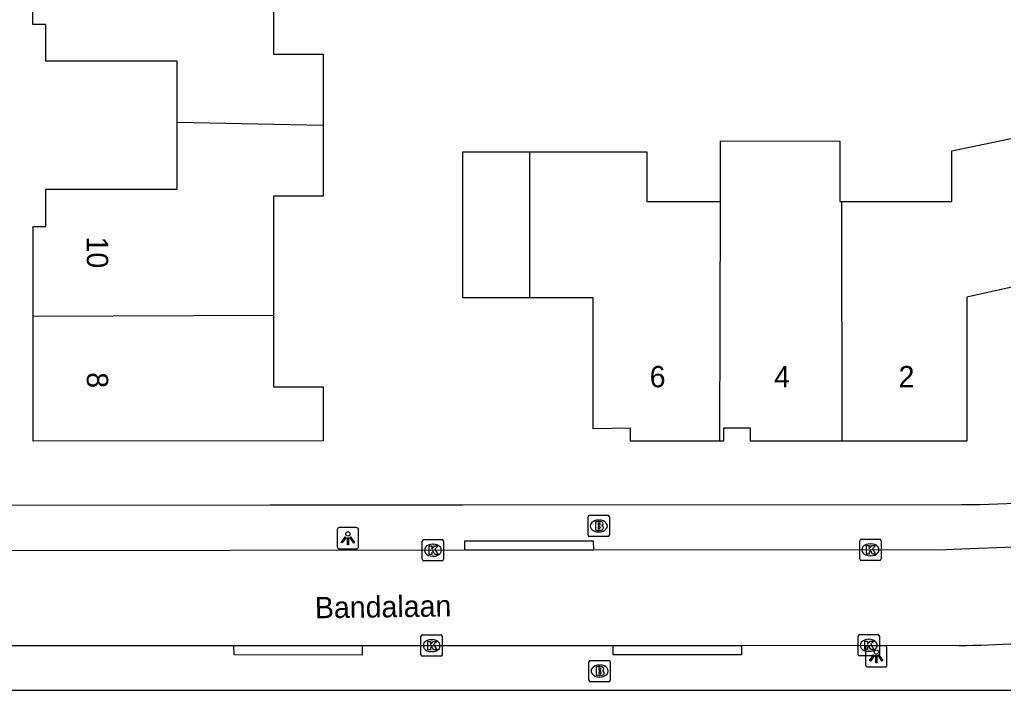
# Model space of a CAD drawing. Extents: x 162880 to 165536, y 384011 to 385179.
# Drawn here: x 163806.79 to 163852.88, y 384309.18 to 384340.61 of the extents above; entities that cross this region are included whole.
import ezdxf

# ---------------------------------------------------------------- set-up
doc = ezdxf.new("R2010")
doc.units = 0
for name, color, linetype in [('IMGEO_Brandkraan', 7, 'Continuous'), ('IMGEO_Kolk', 7, 'Continuous'), ('IMGEO_Lichtpunt', 7, 'Continuous'), ('IMGEO_Muur', 7, 'Continuous'), ('IMGEO_Openbare_ruimte_label', 7, 'Continuous'), ('IMGEO_Pand', 7, 'Continuous'), ('IMGEO_Pand_nummerreeks', 7, 'Continuous'), ('IMGEO_Rijbaan_lokaal_gesloten', 7, 'Continuous'), ('IMGEO_Voetpad_open', 7, 'Continuous')]:
    doc.layers.add(name, color=color, linetype=linetype)

msp = doc.modelspace()

# ---------------------------------------------------------------- linework, layer by layer
at = {"layer": 'IMGEO_Brandkraan'}
for p, q in [((163833.422, 384316.46), (163833.422, 384317.312)), ((163833.497, 384317.386), (163834.349, 384317.386)), ((163833.91, 384317.166), (163833.935, 384317.166)), ((163834.423, 384317.312), (163834.423, 384316.46)), ((163834.349, 384316.386), (163833.497, 384316.386)), ((163833.933, 384316.606), (163833.908, 384316.606)), ((163833.459, 384309.662), (163833.459, 384310.514)), ((163833.534, 384310.588), (163834.386, 384310.588)), ((163833.947, 384310.368), (163833.972, 384310.368)), ((163834.46, 384310.514), (163834.46, 384309.662)), ((163833.97, 384309.808), (163833.945, 384309.808)), ((163834.386, 384309.588), (163833.534, 384309.588))]:
    msp.add_line(p, q, dxfattribs=at)
for points in [[(163833.422, 384316.46), (163833.422, 384317.312)], [(163833.497, 384317.386), (163834.349, 384317.386)], [(163834.423, 384317.312), (163834.423, 384316.46)], [(163833.77, 384317.086), (163833.77, 384316.686), (163833.983, 384316.686)], [(163834.001, 384317.086), (163833.77, 384317.086)], [(163833.949, 384317.005), (163833.895, 384317.005), (163833.895, 384316.929)], [(163833.895, 384316.929), (163833.948, 384316.929)], [(163833.957, 384316.853), (163833.895, 384316.853), (163833.895, 384316.772)], [(163833.895, 384316.772), (163833.957, 384316.772)], [(163834.349, 384316.386), (163833.497, 384316.386)], [(163833.459, 384309.662), (163833.459, 384310.514)], [(163833.534, 384310.588), (163834.386, 384310.588)], [(163833.807, 384310.288), (163833.807, 384309.888), (163834.02, 384309.888)], [(163834.038, 384310.288), (163833.807, 384310.288)], [(163834.46, 384310.514), (163834.46, 384309.662)], [(163833.986, 384310.207), (163833.932, 384310.207), (163833.932, 384310.131)], [(163833.932, 384310.131), (163833.985, 384310.131)], [(163833.994, 384310.055), (163833.932, 384310.055), (163833.932, 384309.974)], [(163833.932, 384309.974), (163833.994, 384309.974)], [(163834.386, 384309.588), (163833.534, 384309.588)]]:
    msp.add_lwpolyline(points, dxfattribs=at)
for centre, radius, start, end in [((163833.499, 384317.31), 0.0765, 91.552, 178.448), ((163833.499, 384317.31), 0.0765, 91.552, 178.448), ((163834.347, 384317.31), 0.0765, 1.552, 88.448), ((163834.347, 384317.31), 0.0765, 1.552, 88.448), ((163833.95, 384316.967), 0.0379, 267.8285, 90.9355), ((163833.958, 384316.812), 0.0404, 269.8759, 90.5077), ((163833.989, 384316.937), 0.251, 268.6676, 293.5347), ((163834.005, 384316.941), 0.145, 59.4692, 91.5367), ((163834.03, 384316.988), 0.0922, 285.5137, 58.1501), ((163834.035, 384316.796), 0.105, 301.3115, 78.989), ((163833.499, 384316.462), 0.0765, 181.552, 268.448), ((163833.499, 384316.462), 0.0765, 181.552, 268.448), ((163834.347, 384316.462), 0.0765, 271.552, 358.448), ((163834.347, 384316.462), 0.0765, 271.552, 358.448), ((163833.536, 384310.512), 0.0765, 91.552, 178.448), ((163833.536, 384310.512), 0.0765, 91.552, 178.448), ((163834.042, 384310.143), 0.145, 59.4692, 91.5367), ((163834.067, 384310.19), 0.0922, 285.5137, 58.1501), ((163834.384, 384310.512), 0.0765, 1.552, 88.448), ((163834.384, 384310.512), 0.0765, 1.552, 88.448), ((163833.987, 384310.169), 0.0379, 267.8285, 90.9355), ((163833.995, 384310.014), 0.0404, 269.8759, 90.5077), ((163834.026, 384310.139), 0.251, 268.6676, 293.5347), ((163834.072, 384309.998), 0.105, 301.3115, 78.989), ((163833.536, 384309.664), 0.0765, 181.552, 268.448), ((163833.536, 384309.664), 0.0765, 181.552, 268.448), ((163834.384, 384309.664), 0.0765, 271.552, 358.448), ((163834.384, 384309.664), 0.0765, 271.552, 358.448)]:
    msp.add_arc(centre, radius, start, end, dxfattribs=at)
for centre, major_axis, ratio, start_param, end_param in [((163833.909, 384316.886), (-0.387, 0.002), 0.722429, 4.712389, 7.853982), ((163833.934, 384316.886), (-0.39, 0.002), 0.717154, 1.570796, 4.712389), ((163833.946, 384310.088), (-0.387, 0.002), 0.722429, 4.712389, 7.853982), ((163833.971, 384310.088), (-0.39, 0.002), 0.717154, 1.570796, 4.712389)]:
    msp.add_ellipse(centre, major_axis=major_axis, ratio=ratio, start_param=start_param, end_param=end_param, dxfattribs=at)
at = {"layer": 'IMGEO_Kolk'}
for p, q in [((163825.727, 384316.249), (163826.579, 384316.249)), ((163846.224, 384316.269), (163847.076, 384316.269)), ((163825.652, 384315.323), (163825.652, 384316.175)), ((163826.14, 384316.029), (163826.165, 384316.029)), ((163826.653, 384316.175), (163826.653, 384315.323)), ((163846.149, 384315.343), (163846.149, 384316.195)), ((163846.637, 384316.049), (163846.662, 384316.049)), ((163847.15, 384316.195), (163847.15, 384315.343)), ((163826.163, 384315.469), (163826.138, 384315.469)), ((163846.66, 384315.489), (163846.635, 384315.489)), ((163826.579, 384315.249), (163825.727, 384315.249)), ((163847.076, 384315.269), (163846.224, 384315.269)), ((163825.591, 384310.852), (163825.591, 384311.704)), ((163825.666, 384311.778), (163826.518, 384311.778)), ((163826.592, 384311.704), (163826.592, 384310.852)), ((163846.071, 384310.869), (163846.071, 384311.721)), ((163846.146, 384311.795), (163846.998, 384311.795)), ((163847.072, 384311.721), (163847.072, 384310.869)), ((163826.079, 384311.558), (163826.104, 384311.558)), ((163846.559, 384311.575), (163846.584, 384311.575)), ((163826.518, 384310.778), (163825.666, 384310.778)), ((163826.102, 384310.998), (163826.077, 384310.998)), ((163846.998, 384310.795), (163846.146, 384310.795)), ((163846.582, 384311.015), (163846.557, 384311.015))]:
    msp.add_line(p, q, dxfattribs=at)
for points in [[(163825.727, 384316.249), (163826.579, 384316.249)], [(163846.224, 384316.269), (163847.076, 384316.269)], [(163825.652, 384315.323), (163825.652, 384316.175)], [(163825.973, 384315.949), (163826.096, 384315.949), (163826.096, 384315.798), (163826.226, 384315.949), (163826.39, 384315.949), (163826.244, 384315.798), (163826.397, 384315.549), (163826.245, 384315.549), (163826.16, 384315.713), (163826.096, 384315.646), (163826.096, 384315.549), (163825.973, 384315.549), (163825.973, 384315.949)], [(163826.653, 384316.175), (163826.653, 384315.323)], [(163846.149, 384315.343), (163846.149, 384316.195)], [(163846.47, 384315.969), (163846.593, 384315.969), (163846.593, 384315.818), (163846.723, 384315.969), (163846.887, 384315.969), (163846.741, 384315.818), (163846.894, 384315.569), (163846.742, 384315.569), (163846.657, 384315.733), (163846.593, 384315.666), (163846.593, 384315.569), (163846.47, 384315.569), (163846.47, 384315.969)], [(163847.15, 384316.195), (163847.15, 384315.343)], [(163826.579, 384315.249), (163825.727, 384315.249)], [(163847.076, 384315.269), (163846.224, 384315.269)], [(163825.591, 384310.852), (163825.591, 384311.704)], [(163825.666, 384311.778), (163826.518, 384311.778)], [(163826.592, 384311.704), (163826.592, 384310.852)], [(163846.071, 384310.869), (163846.071, 384311.721)], [(163846.146, 384311.795), (163846.998, 384311.795)], [(163847.072, 384311.721), (163847.072, 384310.869)], [(163825.912, 384311.478), (163826.035, 384311.478), (163826.035, 384311.327), (163826.165, 384311.478), (163826.329, 384311.478), (163826.183, 384311.327), (163826.336, 384311.078), (163826.184, 384311.078), (163826.099, 384311.242), (163826.035, 384311.175), (163826.035, 384311.078), (163825.912, 384311.078), (163825.912, 384311.478)], [(163846.392, 384311.495), (163846.515, 384311.495), (163846.515, 384311.344), (163846.645, 384311.495), (163846.809, 384311.495), (163846.663, 384311.344), (163846.816, 384311.095), (163846.664, 384311.095), (163846.579, 384311.259), (163846.515, 384311.192), (163846.515, 384311.095), (163846.392, 384311.095), (163846.392, 384311.495)], [(163826.518, 384310.778), (163825.666, 384310.778)], [(163846.998, 384310.795), (163846.146, 384310.795)]]:
    msp.add_lwpolyline(points, dxfattribs=at)
for centre, start, end in [((163825.729, 384316.173), 91.552, 178.448), ((163825.729, 384316.173), 91.552, 178.448), ((163826.577, 384316.173), 1.552, 88.448), ((163826.577, 384316.173), 1.552, 88.448), ((163846.226, 384316.193), 91.552, 178.448), ((163846.226, 384316.193), 91.552, 178.448), ((163847.074, 384316.193), 1.552, 88.448), ((163847.074, 384316.193), 1.552, 88.448), ((163825.729, 384315.325), 181.552, 268.448), ((163825.729, 384315.325), 181.552, 268.448), ((163826.577, 384315.325), 271.552, 358.448), ((163826.577, 384315.325), 271.552, 358.448), ((163846.226, 384315.345), 181.552, 268.448), ((163846.226, 384315.345), 181.552, 268.448), ((163847.074, 384315.345), 271.552, 358.448), ((163847.074, 384315.345), 271.552, 358.448), ((163825.668, 384311.702), 91.552, 178.448), ((163825.668, 384311.702), 91.552, 178.448), ((163826.516, 384311.702), 1.552, 88.448), ((163826.516, 384311.702), 1.552, 88.448), ((163846.148, 384311.719), 91.552, 178.448), ((163846.148, 384311.719), 91.552, 178.448), ((163846.996, 384311.719), 1.552, 88.448), ((163846.996, 384311.719), 1.552, 88.448), ((163825.668, 384310.854), 181.552, 268.448), ((163825.668, 384310.854), 181.552, 268.448), ((163826.516, 384310.854), 271.552, 358.448), ((163826.516, 384310.854), 271.552, 358.448), ((163846.148, 384310.871), 181.552, 268.448), ((163846.148, 384310.871), 181.552, 268.448), ((163846.996, 384310.871), 271.552, 358.448), ((163846.996, 384310.871), 271.552, 358.448)]:
    msp.add_arc(centre, 0.0765, start, end, dxfattribs=at)
for centre, major_axis, ratio, start_param, end_param in [((163826.139, 384315.749), (-0.387, 0.002), 0.722429, 4.712389, 7.853982), ((163826.164, 384315.749), (-0.39, 0.002), 0.717154, 1.570796, 4.712389), ((163846.636, 384315.769), (-0.387, 0.002), 0.722429, 4.712389, 7.853982), ((163846.661, 384315.769), (-0.39, 0.002), 0.717154, 1.570796, 4.712389), ((163826.078, 384311.278), (-0.387, 0.002), 0.722429, 4.712389, 7.853982), ((163826.103, 384311.278), (-0.39, 0.002), 0.717154, 1.570796, 4.712389), ((163846.558, 384311.295), (-0.387, 0.002), 0.722429, 4.712389, 7.853982), ((163846.583, 384311.295), (-0.39, 0.002), 0.717154, 1.570796, 4.712389)]:
    msp.add_ellipse(centre, major_axis=major_axis, ratio=ratio, start_param=start_param, end_param=end_param, dxfattribs=at)
at = {"layer": 'IMGEO_Lichtpunt'}
for p, q in [((163821.669, 384316.715), (163821.669, 384315.908)), ((163821.669, 384316.715), (163821.669, 384315.908)), ((163822.571, 384316.81), (163821.763, 384316.81)), ((163822.571, 384316.81), (163821.763, 384316.81)), ((163822.665, 384315.908), (163822.665, 384316.715)), ((163822.665, 384315.908), (163822.665, 384316.715)), ((163821.763, 384315.814), (163822.571, 384315.814)), ((163821.763, 384315.814), (163822.571, 384315.814)), ((163846.427, 384311.179), (163846.427, 384310.372)), ((163846.427, 384311.179), (163846.427, 384310.372)), ((163847.329, 384311.274), (163846.521, 384311.274)), ((163847.329, 384311.274), (163846.521, 384311.274)), ((163847.423, 384310.372), (163847.423, 384311.179)), ((163847.423, 384310.372), (163847.423, 384311.179)), ((163846.521, 384310.278), (163847.329, 384310.278)), ((163846.521, 384310.278), (163847.329, 384310.278))]:
    msp.add_line(p, q, dxfattribs=at)
for points in [[(163822.043, 384316.379), (163822.082, 384316.351), (163821.894, 384316.089), (163821.856, 384316.116), (163822.043, 384316.379)], [(163822.145, 384316.331), (163822.192, 384316.331), (163822.192, 384316.009), (163822.145, 384316.009), (163822.145, 384316.331)], [(163822.255, 384316.351), (163822.293, 384316.378), (163822.48, 384316.116), (163822.441, 384316.088), (163822.255, 384316.351)], [(163846.801, 384310.843), (163846.84, 384310.815), (163846.652, 384310.553), (163846.614, 384310.58), (163846.801, 384310.843)], [(163846.903, 384310.795), (163846.95, 384310.795), (163846.95, 384310.473), (163846.903, 384310.473), (163846.903, 384310.795)], [(163847.013, 384310.815), (163847.051, 384310.842), (163847.238, 384310.58), (163847.199, 384310.552), (163847.013, 384310.815)]]:
    msp.add_lwpolyline(points, dxfattribs=at)
for centre in [(163822.168, 384316.513), (163846.926, 384310.977)]:
    msp.add_circle(centre, 0.0994, dxfattribs=at)
for centre, start, end in [((163821.763, 384316.715), 90, 180), ((163821.763, 384316.715), 90, 180), ((163822.571, 384316.715), 0, 90), ((163822.571, 384316.715), 0, 90), ((163821.763, 384315.908), 180, 270), ((163821.763, 384315.908), 180, 270), ((163822.571, 384315.908), 270, 0), ((163822.571, 384315.908), 270, 360), ((163846.521, 384311.179), 90, 180), ((163846.521, 384311.179), 90, 180), ((163847.329, 384311.179), 0, 90), ((163847.329, 384311.179), 0, 90), ((163846.521, 384310.372), 180, 270), ((163846.521, 384310.372), 180, 270), ((163847.329, 384310.372), 270, 0), ((163847.329, 384310.372), 270, 360)]:
    msp.add_arc(centre, 0.0946, start, end, dxfattribs=at)
at = {"layer": 'IMGEO_Muur'}
msp.add_lwpolyline([(163818.502, 384317.874), (163827.552, 384317.88)], dxfattribs=at)
at = {"layer": 'IMGEO_Pand'}
for points in [[(163814.163, 384335.79), (163814.163, 384338.662), (163808.008, 384338.663), (163808.008, 384340.393), (163807.408, 384340.393), (163807.408, 384344.433)], [(163818.676, 384344.414), (163818.677, 384339.004), (163821.006, 384339.004), (163821.007, 384335.651)], [(163807.416, 384326.707), (163807.415, 384330.918), (163808.011, 384330.918), (163808.011, 384332.668), (163814.163, 384332.668), (163814.163, 384335.61), (163814.163, 384335.79)], [(163821.007, 384335.651), (163814.163, 384335.79)], [(163821.007, 384335.651), (163821.008, 384332.344), (163818.678, 384332.343), (163818.68, 384326.744)], [(163839.623, 384332.091), (163839.629, 384334.933), (163845.209, 384334.922), (163845.213, 384332.091), (163845.313, 384332.091)], [(163845.313, 384332.091), (163850.472, 384332.091), (163850.471, 384334.461), (163853.547, 384335.107)], [(163830.683, 384327.581), (163827.552, 384327.581), (163827.552, 384334.421), (163830.675, 384334.421)], [(163830.675, 384334.421), (163830.683, 384327.581)], [(163830.675, 384334.421), (163836.172, 384334.421), (163836.172, 384332.091), (163839.623, 384332.091)], [(163839.601, 384320.866), (163839.623, 384332.091)], [(163845.333, 384320.866), (163845.313, 384332.091)], [(163855.03, 384328.471), (163851.161, 384327.615), (163851.16, 384320.865), (163845.333, 384320.866)], [(163839.601, 384320.866), (163835.411, 384320.867), (163835.412, 384321.467), (163833.665, 384321.441), (163833.662, 384327.581), (163830.683, 384327.581)], [(163818.68, 384326.744), (163807.416, 384326.707)], [(163818.68, 384326.744), (163818.681, 384323.413), (163821.01, 384323.413), (163821.01, 384320.873), (163807.418, 384320.868), (163807.416, 384326.707)], [(163845.333, 384320.866), (163841.031, 384320.866), (163841.032, 384321.467), (163839.772, 384321.467), (163839.771, 384320.866), (163839.601, 384320.866)]]:
    msp.add_lwpolyline(points, dxfattribs=at)
at = {"layer": 'IMGEO_Rijbaan_lokaal_gesloten'}
for points in [[(163853.829, 384315.916), (163850.892, 384315.8), (163849.869, 384315.76), (163846.65, 384315.767), (163833.677, 384315.759)], [(163827.642, 384315.751), (163805.669, 384315.721), (163804.751, 384315.73)], [(163833.677, 384315.759), (163827.642, 384315.751)], [(163805.351, 384311.277), (163805.583, 384311.283), (163816.821, 384311.291)], [(163816.821, 384311.291), (163822.842, 384311.282)], [(163822.842, 384311.282), (163826.092, 384311.279), (163834.592, 384311.29)], [(163834.592, 384311.29), (163840.613, 384311.28)], [(163840.613, 384311.28), (163846.571, 384311.296), (163850.798, 384311.287)]]:
    msp.add_lwpolyline(points, dxfattribs=at)
msp.add_arc((163850.172, 384369.286), 58.002, 270.61824, 276.09038, dxfattribs=at)
at = {"layer": 'IMGEO_Voetpad_open'}
for points in [[(163805.519, 384317.866), (163818.502, 384317.874), (163827.552, 384317.88), (163850.936, 384317.894)], [(163827.642, 384315.751), (163827.652, 384316.187), (163833.663, 384316.19), (163833.677, 384315.759)], [(163822.842, 384311.282), (163822.842, 384310.833), (163816.835, 384310.847), (163816.821, 384311.291)], [(163840.613, 384311.28), (163840.609, 384310.841), (163834.604, 384310.845), (163834.592, 384311.29)], [(163801.871, 384309.184), (163850.754, 384309.197), (163858.049, 384309.199)]]:
    msp.add_lwpolyline(points, dxfattribs=at)
msp.add_arc((163851.374, 384345.148), 27.258, 269.0783, 297.3115, dxfattribs=at)

# ---------------------------------------------------------------- texts
at = {"layer": 'IMGEO_Openbare_ruimte_label'}
msp.add_text('Bandalaan', height=1, rotation=0.8021, dxfattribs=at).set_placement((163820.625, 384312.558))
at = {"layer": 'IMGEO_Pand_nummerreeks'}
for s, rotation, p in [('10', 270.0171, (163809.935, 384330.451)), ('6', 359.9921, (163836.306, 384323.387)), ('4', 359.9943, (163842.138, 384323.386)), ('2', 359.9921, (163847.968, 384323.385)), ('8', 270.0171, (163809.937, 384324.09))]:
    msp.add_text(s, height=1, rotation=rotation, dxfattribs=at).set_placement(p)

doc.saveas('drawing.dxf')
